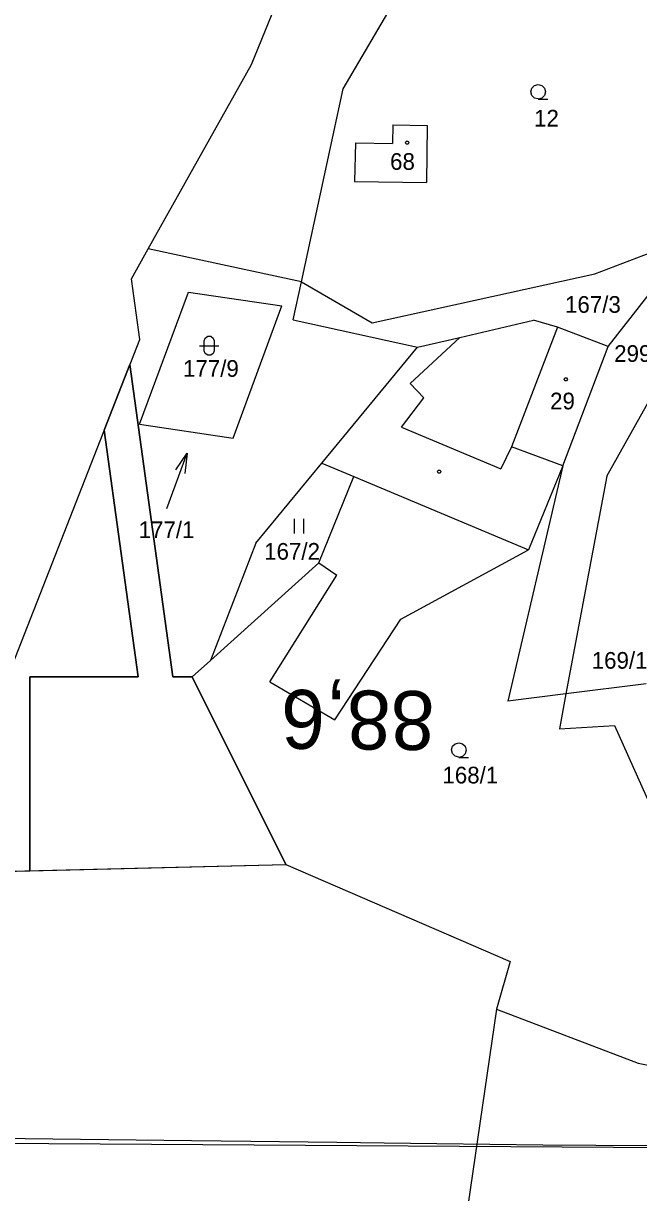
# Model space of a CAD drawing. Extents: x -780000 to -777378, y -1011169 to -1009297.
# Drawn here: x -779250.3 to -779187.7, y -1010479.3 to -1010360.1 of the extents above; entities that cross this region are included whole.
import ezdxf

# ---------------------------------------------------------------- set-up
doc = ezdxf.new("R2010")
doc.units = 0
for name, color, linetype in [('Default', 7, 'Continuous'), ('KN_HRANICE', 7, 'Continuous'), ('KN_KULTURY', 7, 'Continuous'), ('KN_PARCELY', 7, 'Continuous'), ('KN_SLUCKY', 7, 'Continuous'), ('KN_VEDENI', 7, 'Continuous'), ('obvod_stavby', 7, 'Continuous'), ('vlastníci', 7, 'Continuous'), ('Vrstva 7', 7, 'Continuous'), ('Železniční svršek', 7, 'Continuous')]:
    doc.layers.add(name, color=color, linetype=linetype)

# ---------------------------------------------------------------- blocks, each defined once
blk = doc.blocks.new('304')
at = {"layer": 'Default'}
blk.add_lwpolyline([(0, 0), (-0.38, 0.1), (-0.65, 0.37), (-0.75, 0.74), (-0.65, 1.11), (-0.38, 1.38), (-0.01, 1.48), (0.36, 1.38), (0.63, 1.11), (0.73, 0.73), (0.63, 0.35), (0.36, 0.08), (-0.02, -0.02), (0.98, -0.02)], dxfattribs=at)
blk = doc.blocks.new('306')
at = {"layer": 'Default'}
for p, q in [((-0.5, 1.5), (-0.5, 0)), ((0.5, 0), (0.5, 1.5))]:
    blk.add_line(p, q, dxfattribs=at)
blk = doc.blocks.new('316')
at = {"layer": 'Default'}
for points in [[(-0.5, 1.5), (-0.4, 1.79), (-0.15, 1.97), (0.16, 1.97), (0.41, 1.79), (0.51, 1.5), (0.51, 0.5), (0.41, 0.21), (0.16, 0.03), (-0.15, 0.03), (-0.4, 0.21), (-0.5, 0.5), (-0.5, 1.5)], [(-1, 1), (0.27, 1), (1, 1)]]:
    blk.add_lwpolyline(points, dxfattribs=at)
blk = doc.blocks.new('802')
at = {"layer": 'Default'}
blk.add_line((-3, 0), (3, 0), dxfattribs=at)
blk.add_lwpolyline([(1, 0.5), (3, 0), (1, -0.5)], dxfattribs=at)
blk = doc.blocks.new('402')
at = {"layer": 'Default'}
blk.add_lwpolyline([(0.09, 0.15), (0.18, 0), (0.09, -0.15), (-0.09, -0.15), (-0.18, 0), (-0.09, 0.15), (0.09, 0.15)], dxfattribs=at)

msp = doc.modelspace()

# ---------------------------------------------------------------- linework, layer by layer
at = {"layer": 'KN_HRANICE'}
for p, q in [((-779227.1, -1010364.33), (-779217.17, -1010339.95)), ((-779217.76, -1010366.81), (-779204.93, -1010344.94)), ((-779237.61, -1010383.13), (-779227.1, -1010364.33)), ((-779222.02, -1010386.49), (-779217.76, -1010366.81)), ((-779212.71, -1010370.47), (-779212.73, -1010372.38)), ((-779212.71, -1010370.47), (-779209.21, -1010370.54)), ((-779209.21, -1010370.54), (-779209.28, -1010376.35)), ((-779216.52, -1010372.33), (-779216.59, -1010376.27)), ((-779216.52, -1010372.33), (-779212.73, -1010372.38)), ((-779216.59, -1010376.27), (-779209.28, -1010376.35)), ((-779192.12, -1010385.68), (-779181.94, -1010381.76)), ((-779190.77, -1010393.08), (-779181.94, -1010381.76)), ((-779239.31, -1010386.18), (-779237.61, -1010383.13)), ((-779222.02, -1010386.49), (-779237.61, -1010383.13)), ((-779214.8, -1010390.67), (-779192.12, -1010385.68)), ((-779238.48, -1010392.35), (-779239.31, -1010386.18)), ((-779222.86, -1010390.35), (-779222.02, -1010386.49)), ((-779222.02, -1010386.49), (-779214.8, -1010390.67)), ((-779238.5, -1010401), (-779233.52, -1010387.55)), ((-779233.52, -1010387.55), (-779224.02, -1010388.94)), ((-779190.91, -1010406.29), (-779180.32, -1010387.37)), ((-779228.95, -1010402.41), (-779224.02, -1010388.94)), ((-779222.86, -1010390.35), (-779210.18, -1010393.14)), ((-779205.88, -1010392.14), (-779198.36, -1010390.38)), ((-779195.92, -1010391.11), (-779198.36, -1010390.38)), ((-779190.77, -1010393.08), (-779195.92, -1010391.11)), ((-779257.31, -1010440.46), (-779238.48, -1010392.35)), ((-779210.18, -1010393.14), (-779205.88, -1010392.14)), ((-779219.94, -1010404.96), (-779210.18, -1010393.14)), ((-779195.38, -1010405.25), (-779190.77, -1010393.08)), ((-779238.5, -1010401), (-779228.95, -1010402.41)), ((-779226.66, -1010413.11), (-779219.94, -1010404.96)), ((-779219.94, -1010404.96), (-779216.67, -1010406.33)), ((-779195.38, -1010405.25), (-779201, -1010429.21)), ((-779195.38, -1010405.25), (-779198.89, -1010413.78)), ((-779220.25, -1010415.13), (-779216.67, -1010406.33)), ((-779190.91, -1010406.29), (-779195.06, -1010428.47)), ((-779226.66, -1010413.11), (-779231.29, -1010425.07)), ((-779211.9, -1010420.85), (-779198.89, -1010413.78)), ((-779220.25, -1010415.13), (-779231.29, -1010425.07)), ((-779220.25, -1010415.13), (-779218.42, -1010416.38)), ((-779225.24, -1010427.24), (-779218.42, -1010416.38)), ((-779218.62, -1010431.11), (-779211.9, -1010420.85)), ((-779231.29, -1010425.07), (-779233.15, -1010426.74)), ((-779223.61, -1010445.86), (-779233.15, -1010426.74)), ((-779225.24, -1010427.24), (-779218.62, -1010431.11)), ((-779186.88, -1010427.45), (-779195.06, -1010428.47)), ((-779195.06, -1010428.47), (-779201, -1010429.21)), ((-779195.06, -1010428.47), (-779195.73, -1010432.05)), ((-779195.73, -1010432.05), (-779190.11, -1010431.7)), ((-779190.11, -1010431.7), (-779181.17, -1010451.77)), ((-779255.18, -1010446.63), (-779223.61, -1010445.86)), ((-779223.61, -1010445.86), (-779200.73, -1010455.74)), ((-779200.73, -1010455.74), (-779202.13, -1010460.62)), ((-779202.13, -1010460.62), (-779187.71, -1010466.11)), ((-779187.71, -1010466.11), (-779165.75, -1010470.45))]:
    msp.add_line(p, q, dxfattribs=at)
at = {"layer": 'KN_SLUCKY'}
for p, q in [((-779195.92, -1010391.11), (-779200.6, -1010403.31)), ((-779210.93, -1010396.85), (-779205.88, -1010392.14)), ((-779210.93, -1010396.85), (-779209.53, -1010398.31)), ((-779211.82, -1010401.29), (-779209.53, -1010398.31)), ((-779211.82, -1010401.29), (-779201.69, -1010405.54)), ((-779200.6, -1010403.31), (-779201.69, -1010405.54)), ((-779195.38, -1010405.25), (-779200.6, -1010403.31)), ((-779216.67, -1010406.33), (-779198.89, -1010413.78))]:
    msp.add_line(p, q, dxfattribs=at)
at = {"layer": 'KN_VEDENI'}
msp.add_line((-779395.56, -1010473.38), (-779130.44, -1010475.03), dxfattribs=at)
at = {"layer": 'obvod_stavby'}
msp.add_lwpolyline([(-779249.69, -1010446.5), (-779249.69, -1010426.74), (-779238.66, -1010426.74), (-779242.1, -1010401.61), (-779239.48, -1010394.92), (-779235.13, -1010426.74), (-779233.15, -1010426.74), (-779223.61, -1010445.86), (-779200.73, -1010455.74), (-779202.13, -1010460.62), (-779207.48, -1010497.19), (-779226.1, -1010504.31), (-779235.46, -1010501.42), (-779255.21, -1010502.98), (-779255.18, -1010446.63), (-779249.69, -1010446.5)], dxfattribs=at)
at = {"layer": 'vlastníci'}
msp.add_lwpolyline([(-779242.1, -1010401.61), (-779238.66, -1010426.74), (-779249.69, -1010426.74), (-779249.69, -1010446.5), (-779223.61, -1010445.86), (-779233.15, -1010426.74), (-779235.13, -1010426.74), (-779239.48, -1010394.92)], close=True, dxfattribs=at)
at = {"layer": 'Železniční svršek'}
for p, q in [((-779233.21, -1010474.03), (-779254.8, -1010473.76)), ((-779227.16, -1010474.09), (-779233.21, -1010474.03)), ((-779218.4, -1010474.21), (-779227.16, -1010474.09)), ((-779213.59, -1010474.26), (-779218.4, -1010474.21)), ((-779208.23, -1010474.32), (-779213.59, -1010474.26)), ((-779197.43, -1010474.45), (-779208.23, -1010474.32))]:
    msp.add_line(p, q, dxfattribs=at)
msp.add_lwpolyline([(-779186.63, -1010474.52), (-779197.43, -1010474.45)], dxfattribs=at)

# ---------------------------------------------------------------- block references
at = {"layer": 'KN_KULTURY'}
for name, p in [('304', (-779197.89, -1010367.85)), ('402', (-779211.24, -1010372.3)), ('316', (-779231.41, -1010394)), ('402', (-779195.08, -1010396.43)), ('402', (-779207.98, -1010405.83)), ('306', (-779222.25, -1010412.13)), ('304', (-779205.96, -1010434.93))]:
    msp.add_blockref(name, p, dxfattribs=at)
at = {"layer": 'KN_KULTURY', "rotation": 69.728964}
msp.add_blockref('802', (-779234.7, -1010406.77), dxfattribs=at)

# ---------------------------------------------------------------- texts
at = {"layer": 'KN_PARCELY'}
for s, p in [('12', (-779198.31, -1010370.66)), ('68', (-779212.98, -1010375.07)), ('167/3', (-779195.16, -1010389.64)), ('299/1', (-779190.15, -1010394.64)), ('177/9', (-779234.08, -1010396.16)), ('29', (-779196.68, -1010399.48)), ('177/1', (-779238.6, -1010412.6)), ('167/2', (-779225.81, -1010414.8)), ('169/1', (-779192.44, -1010425.91)), ('168/1', (-779207.65, -1010437.6))]:
    msp.add_text(s, height=1.7, dxfattribs=at).set_placement(p)
at = {"layer": 'Vrstva 7'}
msp.add_text('88,6', height=6, rotation=179.4159, dxfattribs=at).set_placement((-779208.42, -1010428.21))

doc.saveas('drawing.dxf')
